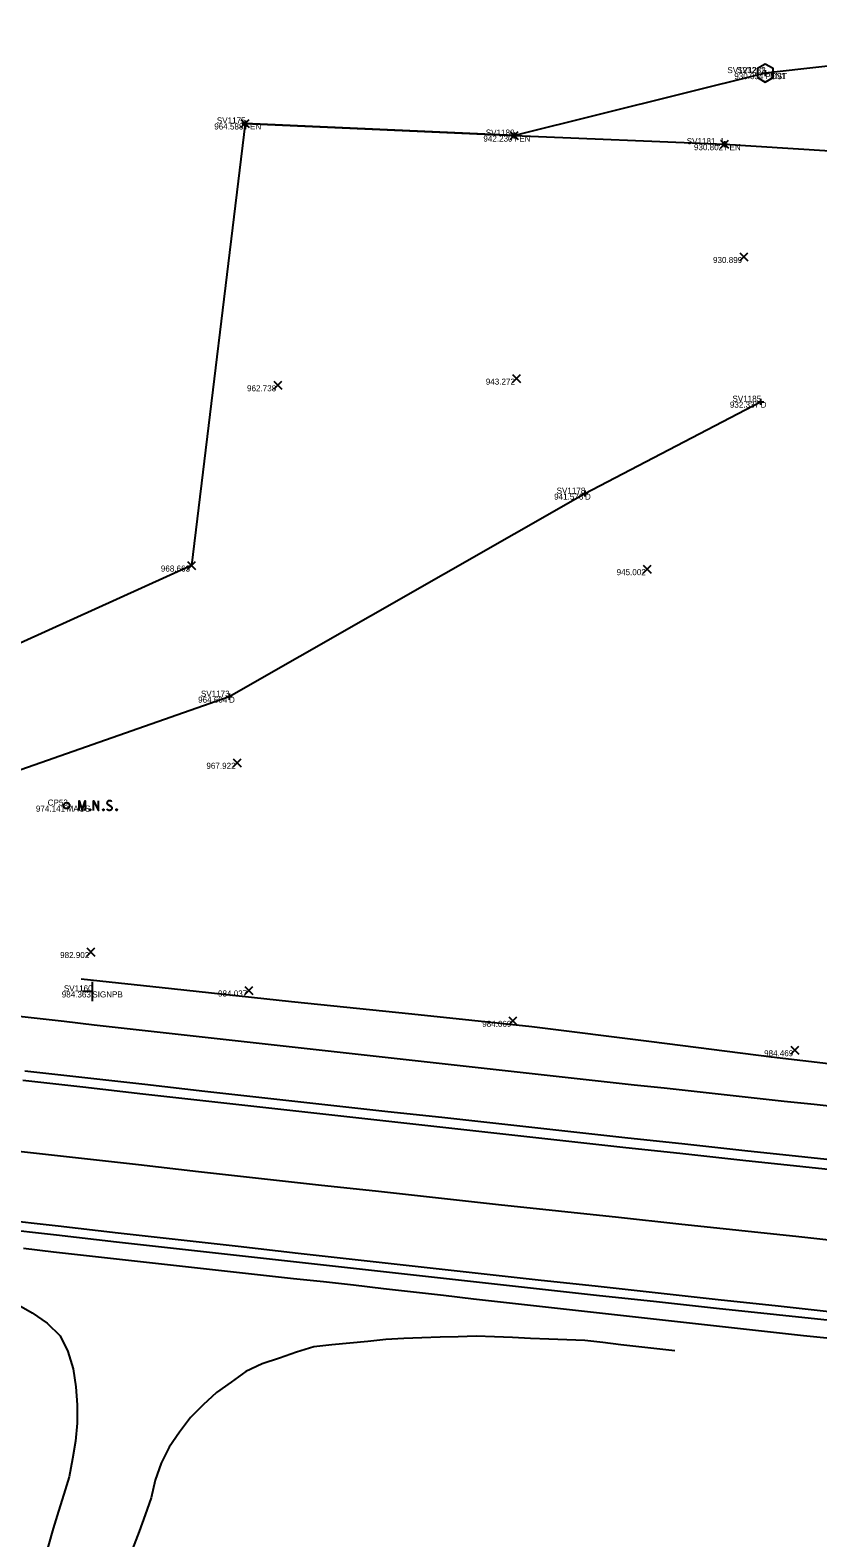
# Model space of a CAD drawing. Extents: x 2065431 to 2068157, y 709104 to 709719.
# Drawn here: x 2067117.5 to 2067248, y 709378.9 to 709628.4 of the extents above; entities that cross this region are included whole.
import ezdxf

# ---------------------------------------------------------------- set-up
doc = ezdxf.new("R2010")
doc.units = 0
for name, color, linetype in [('DT_X_Break_Line', 7, 'Continuous'), ('DT_X_Terrain_Boundary', 7, 'Continuous'), ('PM_X_Edge_Line', 7, 'Continuous'), ('PM_X_Lane_Line', 7, 'Continuous'), ('PV_X_EOP', 7, 'Continuous'), ('PV_X_Shoulder_Rumble_Strip', 7, 'Continuous'), ('RD_X_Fence', 7, 'Continuous'), ('RS_Raster1', 7, 'Continuous'), ('RW_X_CL_100_Bearings', 7, 'Continuous'), ('RW_X_CL_100_Cardinal_Points', 7, 'Continuous'), ('RW_X_CL_100_Curve_Data', 7, 'Continuous'), ('RW_X_CL_100_Distances', 7, 'Continuous'), ('RW_X_Fee_WL', 7, 'Continuous'), ('SV_X_Mon_Cells_Found', 7, 'Continuous'), ('SV_X_Text_Elevation', 7, 'Continuous'), ('SV_X_Text_Name', 7, 'Continuous')]:
    doc.layers.add(name, color=color, linetype=linetype)

msp = doc.modelspace()

# ---------------------------------------------------------------- linework, layer by layer
at = {"layer": 'DT_X_Break_Line'}
msp.add_lwpolyline([(2067498.75, 709430.51), (2067478.87, 709432.67), (2067458.99, 709434.82), (2067439.1, 709436.98), (2067419.22, 709439.13), (2067399.35, 709441.43), (2067379.49, 709443.77), (2067359.59, 709445.77), (2067339.67, 709447.56), (2067319.78, 709449.65), (2067299.9, 709451.81), (2067280.01, 709453.96), (2067260.13, 709456.11), (2067240.26, 709458.41), (2067220.42, 709460.94), (2067200.58, 709463.45), (2067180.69, 709465.52), (2067160.8, 709467.59), (2067140.91, 709469.71), (2067125.91, 709471.33)], dxfattribs=at)
at = {"layer": 'DT_X_Terrain_Boundary'}
msp.add_lwpolyline([(2067560.73, 709418.79), (2067495.34, 709436.29), (2067456.65, 709439.38), (2067410.67, 709443.42), (2067361.02, 709524.1), (2067366.41, 709549.95), (2067373.99, 709596.43), (2067354.6, 709616.29), (2067311.55, 709621.56), (2067309.4, 709622.8), (2067308.24, 709625.52), (2067305.17, 709625.78), (2067302.95, 709628.43), (2067239.24, 709621.32), (2067197.78, 709611.01), (2067153.08, 709612.99), (2067144.2, 709539.81), (2067080.32, 709510.92)], dxfattribs=at)
at = {"layer": 'PM_X_Edge_Line'}
for points in [[(2067116.29, 709454.61), (2067126.22, 709453.49), (2067136.16, 709452.37), (2067146.1, 709451.25), (2067156.04, 709450.14), (2067165.98, 709449.03), (2067175.91, 709447.93), (2067185.85, 709446.83), (2067195.79, 709445.73), (2067205.73, 709444.64), (2067215.67, 709443.55), (2067225.62, 709442.47), (2067235.56, 709441.4), (2067245.5, 709440.32), (2067255.44, 709439.26)], [(2067112.19, 709431.63), (2067122.13, 709430.5), (2067132.07, 709429.37), (2067142, 709428.24), (2067151.94, 709427.12), (2067161.88, 709426), (2067171.81, 709424.89), (2067181.75, 709423.78), (2067191.69, 709422.68), (2067201.63, 709421.58), (2067211.57, 709420.49), (2067221.51, 709419.41), (2067231.45, 709418.33), (2067241.4, 709417.25), (2067251.34, 709416.18)]]:
    msp.add_lwpolyline(points, dxfattribs=at)
at = {"layer": 'PM_X_Lane_Line'}
msp.add_lwpolyline([(2067115.57, 709442.89), (2067125.5, 709441.77), (2067135.44, 709440.64), (2067145.38, 709439.52), (2067155.32, 709438.4), (2067165.25, 709437.3), (2067175.2, 709436.22), (2067185.14, 709435.14), (2067195.08, 709434.06), (2067205.02, 709432.99), (2067214.96, 709431.92), (2067224.91, 709430.85), (2067234.85, 709429.78), (2067244.79, 709428.71), (2067254.74, 709427.65)], dxfattribs=at)
at = {"layer": 'PV_X_EOP'}
for points in [[(2067113.17, 709465.49), (2067118.13, 709464.92), (2067123.1, 709464.36), (2067128.07, 709463.8), (2067133.04, 709463.24), (2067138.01, 709462.69), (2067142.98, 709462.13), (2067147.95, 709461.57), (2067152.92, 709461.02), (2067157.88, 709460.47), (2067162.85, 709459.91), (2067167.82, 709459.36), (2067172.79, 709458.81), (2067177.76, 709458.26), (2067182.73, 709457.71), (2067187.7, 709457.15), (2067192.67, 709456.6), (2067197.64, 709456.05), (2067202.61, 709455.51), (2067207.58, 709454.96), (2067212.55, 709454.41), (2067217.52, 709453.87), (2067222.49, 709453.32), (2067227.46, 709452.78), (2067232.43, 709452.24), (2067237.4, 709451.7), (2067242.37, 709451.16), (2067247.34, 709450.62), (2067252.32, 709450.08)], [(2067116.39, 709426.78), (2067121.36, 709426.22), (2067126.33, 709425.67), (2067131.3, 709425.11), (2067136.27, 709424.56), (2067141.24, 709424.01), (2067146.21, 709423.46), (2067151.18, 709422.91), (2067156.15, 709422.36), (2067161.12, 709421.81), (2067166.09, 709421.27), (2067171.06, 709420.71), (2067176.03, 709420.14), (2067180.99, 709419.57), (2067185.96, 709419.01), (2067190.93, 709418.44), (2067195.9, 709417.88), (2067200.87, 709417.32), (2067205.83, 709416.77), (2067210.8, 709416.21), (2067215.77, 709415.66), (2067220.74, 709415.1), (2067225.71, 709414.55), (2067230.68, 709414), (2067235.65, 709413.46), (2067240.62, 709412.91), (2067245.59, 709412.37), (2067250.56, 709411.83)], [(2067115.24, 709417.59), (2067117.83, 709416.08), (2067120.3, 709414.41), (2067122.45, 709412.31), (2067123.73, 709409.68), (2067124.59, 709406.81), (2067125.06, 709403.85), (2067125.25, 709400.86), (2067125.25, 709397.86), (2067124.99, 709394.88), (2067124.49, 709391.92), (2067123.95, 709388.98), (2067123.07, 709386.11), (2067122.18, 709383.25), (2067121.29, 709380.38), (2067120.45, 709377.5), (2067119.6, 709374.62), (2067118.87, 709371.71), (2067118.45, 709368.75), (2067117.47, 709366.07)], [(2067224.28, 709409.82), (2067221.3, 709410.16), (2067218.32, 709410.49), (2067215.33, 709410.83), (2067212.35, 709411.17), (2067209.37, 709411.5), (2067206.37, 709411.62), (2067203.38, 709411.75), (2067200.38, 709411.87), (2067197.38, 709412), (2067194.38, 709412.12), (2067191.39, 709412.25), (2067188.39, 709412.15), (2067185.39, 709412.05), (2067182.39, 709411.94), (2067179.39, 709411.84), (2067176.4, 709411.68), (2067173.41, 709411.38), (2067170.43, 709411.08), (2067167.45, 709410.78), (2067164.46, 709410.48), (2067161.61, 709409.58), (2067158.77, 709408.61), (2067155.93, 709407.64), (2067153.24, 709406.37), (2067150.8, 709404.63), (2067148.35, 709402.9), (2067146.13, 709400.89), (2067144.04, 709398.75), (2067142.23, 709396.35), (2067140.54, 709393.89), (2067139.21, 709391.2), (2067138.17, 709388.41), (2067137.51, 709385.48), (2067136.52, 709382.66), (2067135.52, 709379.9), (2067134.43, 709377.04)]]:
    msp.add_lwpolyline(points, dxfattribs=at)
at = {"layer": 'PV_X_Shoulder_Rumble_Strip'}
for points in [[(2067116.61, 709456.16), (2067126.55, 709455.04), (2067136.48, 709453.93), (2067146.42, 709452.82), (2067156.36, 709451.71), (2067166.3, 709450.61), (2067176.24, 709449.51), (2067186.18, 709448.42), (2067196.12, 709447.32), (2067206.06, 709446.24), (2067216, 709445.15), (2067225.94, 709444.08), (2067235.88, 709443), (2067245.83, 709441.93), (2067255.77, 709440.87)], [(2067111.93, 709430.13), (2067121.87, 709429.01), (2067131.8, 709427.88), (2067141.74, 709426.76), (2067151.68, 709425.65), (2067161.62, 709424.54), (2067171.55, 709423.43), (2067181.49, 709422.33), (2067191.43, 709421.23), (2067201.37, 709420.14), (2067211.31, 709419.05), (2067221.26, 709417.97), (2067231.2, 709416.89), (2067241.14, 709415.82), (2067251.08, 709414.76)]]:
    msp.add_lwpolyline(points, dxfattribs=at)
at = {"layer": 'RD_X_Fence'}
msp.add_lwpolyline([(2067153.08, 709612.99), (2067197.68, 709610.98), (2067232.51, 709609.56), (2067278.02, 709606.69), (2067296.45, 709582.36), (2067311.18, 709565.23)], dxfattribs=at)
at = {"layer": 'RS_Raster1'}
for p, q in [((2067238.74, 709621.32), (2067239.74, 709621.32)), ((2067239.24, 709621.82), (2067239.24, 709620.82)), ((2067239.24, 709621.32), (2067239.24, 709621.32)), ((2067152.58, 709612.99), (2067153.58, 709612.99)), ((2067153.08, 709613.49), (2067153.08, 709612.49)), ((2067153.08, 709612.99), (2067153.08, 709612.99)), ((2067197.68, 709611.48), (2067197.68, 709610.48)), ((2067197.18, 709610.98), (2067198.18, 709610.98)), ((2067197.68, 709610.98), (2067197.68, 709610.98)), ((2067232.01, 709609.56), (2067233.01, 709609.56)), ((2067232.51, 709610.06), (2067232.51, 709609.06)), ((2067232.51, 709609.56), (2067232.51, 709609.56)), ((2067237.99, 709566.93), (2067238.99, 709566.93)), ((2067238.49, 709567.43), (2067238.49, 709566.43)), ((2067238.49, 709566.93), (2067238.49, 709566.93)), ((2067208.89, 709551.71), (2067209.89, 709551.71)), ((2067209.39, 709552.21), (2067209.39, 709551.21)), ((2067209.39, 709551.71), (2067209.39, 709551.71)), ((2067149.93, 709518.1), (2067150.93, 709518.1)), ((2067150.43, 709518.6), (2067150.43, 709517.6)), ((2067150.43, 709518.1), (2067150.43, 709518.1))]:
    msp.add_line(p, q, dxfattribs=at)
at = {"layer": 'RW_X_CL_100_Bearings'}
for p, q in [((2067152.41, 709612.33), (2067153.74, 709613.66)), ((2067152.41, 709613.66), (2067153.74, 709612.33)), ((2067197.01, 709610.32), (2067198.34, 709611.65)), ((2067197.01, 709611.65), (2067198.34, 709610.32)), ((2067231.84, 709608.89), (2067233.18, 709610.23)), ((2067231.84, 709610.23), (2067233.18, 709608.89)), ((2067235.02, 709590.22), (2067236.35, 709591.56)), ((2067235.02, 709591.56), (2067236.35, 709590.22)), ((2067197.37, 709570.08), (2067198.7, 709571.42)), ((2067197.37, 709571.42), (2067198.7, 709570.08)), ((2067157.84, 709568.98), (2067159.17, 709570.32)), ((2067157.84, 709570.32), (2067159.17, 709568.98)), ((2067143.54, 709539.14), (2067144.87, 709540.48)), ((2067143.54, 709540.48), (2067144.87, 709539.14)), ((2067219.04, 709538.55), (2067220.37, 709539.88)), ((2067219.04, 709539.88), (2067220.37, 709538.55)), ((2067151.09, 709506.49), (2067152.42, 709507.83)), ((2067151.09, 709507.83), (2067152.42, 709506.49)), ((2067126.86, 709475.17), (2067128.19, 709476.5)), ((2067126.86, 709476.5), (2067128.19, 709475.17)), ((2067153.04, 709468.8), (2067154.37, 709470.13)), ((2067153.04, 709470.13), (2067154.37, 709468.8)), ((2067196.79, 709463.77), (2067198.12, 709465.11)), ((2067196.79, 709465.11), (2067198.12, 709463.77)), ((2067243.48, 709458.91), (2067244.81, 709460.24)), ((2067243.48, 709460.24), (2067244.81, 709458.91))]:
    msp.add_line(p, q, dxfattribs=at)
at = {"layer": 'RW_X_CL_100_Cardinal_Points'}
for p, q in [((2067127.78, 709469.31), (2067126.18, 709469.31)), ((2067127.78, 709470.91), (2067127.78, 709467.71))]:
    msp.add_line(p, q, dxfattribs=at)
at = {"layer": 'RW_X_CL_100_Curve_Data'}
for points in [[(2067125.61, 709499.27), (2067125.61, 709500.87), (2067126.12, 709499.27), (2067126.6, 709500.87), (2067126.6, 709499.27)], [(2067127.38, 709499.49), (2067127.43, 709499.49), (2067127.46, 709499.46), (2067127.5, 709499.41), (2067127.5, 709499.35), (2067127.46, 709499.3), (2067127.43, 709499.27), (2067127.38, 709499.27), (2067127.34, 709499.3), (2067127.31, 709499.35), (2067127.31, 709499.41), (2067127.34, 709499.46), (2067127.38, 709499.49)], [(2067127.98, 709499.27), (2067127.98, 709500.87), (2067128.81, 709499.27), (2067128.81, 709500.87)], [(2067129.59, 709499.49), (2067129.65, 709499.49), (2067129.68, 709499.46), (2067129.71, 709499.41), (2067129.71, 709499.35), (2067129.68, 709499.3), (2067129.65, 709499.27), (2067129.59, 709499.27), (2067129.56, 709499.3), (2067129.52, 709499.35), (2067129.52, 709499.41), (2067129.56, 709499.46), (2067129.59, 709499.49)], [(2067130.96, 709500.76), (2067130.94, 709500.79), (2067130.9, 709500.81), (2067130.8, 709500.85), (2067130.68, 709500.87), (2067130.59, 709500.87), (2067130.56, 709500.87), (2067130.42, 709500.84), (2067130.3, 709500.76), (2067130.22, 709500.66), (2067130.2, 709500.56), (2067130.2, 709500.48), (2067130.22, 709500.38), (2067130.31, 709500.29), (2067130.91, 709499.92), (2067130.97, 709499.87), (2067130.99, 709499.82), (2067131.01, 709499.74), (2067131.01, 709499.67), (2067131, 709499.59), (2067130.99, 709499.54), (2067130.97, 709499.48), (2067130.95, 709499.43), (2067130.92, 709499.39), (2067130.89, 709499.35), (2067130.86, 709499.32), (2067130.81, 709499.3), (2067130.78, 709499.29), (2067130.68, 709499.27), (2067130.53, 709499.27), (2067130.43, 709499.3), (2067130.29, 709499.39), (2067130.2, 709499.46)], [(2067131.77, 709499.49), (2067131.83, 709499.49), (2067131.86, 709499.46), (2067131.89, 709499.41), (2067131.89, 709499.35), (2067131.86, 709499.3), (2067131.83, 709499.27), (2067131.77, 709499.27), (2067131.74, 709499.3), (2067131.71, 709499.35), (2067131.71, 709499.41), (2067131.74, 709499.46), (2067131.77, 709499.49)]]:
    msp.add_lwpolyline(points, dxfattribs=at)
msp.add_circle((2067123.52, 709500.07), 0.497, dxfattribs=at)
at = {"layer": 'RW_X_CL_100_Distances'}
msp.add_lwpolyline([(2067237.94, 709620.57), (2067239.24, 709619.82), (2067240.54, 709620.57), (2067240.54, 709622.07), (2067239.24, 709622.82), (2067237.94, 709622.07), (2067237.94, 709620.57)], dxfattribs=at)
at = {"layer": 'RW_X_Fee_WL'}
msp.add_lwpolyline([(2066980.58, 709498.86), (2067014.05, 709495.27), (2067044.47, 709492.22), (2067084.68, 709495.12), (2067150.43, 709518.1), (2067209.39, 709551.71), (2067238.49, 709566.93)], dxfattribs=at)

# ---------------------------------------------------------------- texts
at = {"layer": 'SV_X_Mon_Cells_Found'}
for s, p in [('SV1232_1', (2067232.98, 709621.32)), ('SV1232', (2067234.57, 709621.32)), ('SV1175', (2067148.41, 709612.99)), ('SV1180', (2067192.96, 709610.98)), ('SV1181_1', (2067226.25, 709609.56)), ('SV1185', (2067233.82, 709566.93)), ('SV1178', (2067204.69, 709551.71)), ('SV1173', (2067145.77, 709518.1)), ('CP53', (2067120.39, 709500.07)), ('SV1160', (2067123.07, 709469.31))]:
    msp.add_text(s, height=1, dxfattribs=at).set_placement(p)
at = {"layer": 'SV_X_Text_Elevation'}
for s, p in [('POST', (2067239.24, 709620.32)), ('FEN1', (2067239.24, 709620.32)), ('FEN', (2067153.08, 709611.99)), ('FEN', (2067197.68, 709609.98)), ('FEN', (2067232.51, 709608.56)), ('D', (2067238.49, 709565.93)), ('D', (2067209.39, 709550.71)), ('D', (2067150.43, 709517.1)), ('MAGS', (2067123.52, 709499.07)), ('SIGNPB', (2067127.78, 709468.31))]:
    msp.add_text(s, height=1, dxfattribs=at).set_placement(p)
at = {"layer": 'SV_X_Text_Name'}
for s, p in [('930.054', (2067234.12, 709620.32)), ('930.054', (2067234.12, 709620.32)), ('964.588', (2067147.98, 709611.99)), ('964.588', (2067147.98, 709611.99)), ('942.230', (2067192.56, 709609.98)), ('942.230', (2067192.56, 709609.98)), ('930.802', (2067227.44, 709608.56)), ('930.802', (2067227.44, 709608.56)), ('930.899', (2067230.6, 709589.89)), ('962.738', (2067153.41, 709568.65)), ('943.272', (2067192.96, 709569.75)), ('932.337', (2067233.39, 709565.93)), ('941.576', (2067204.28, 709550.71)), ('968.663', (2067139.14, 709538.81)), ('945.002', (2067214.63, 709538.21)), ('964.604', (2067145.31, 709517.1)), ('967.922', (2067146.68, 709506.16)), ('974.141', (2067118.44, 709499.07)), ('982.902', (2067122.45, 709474.83)), ('984.363', (2067122.72, 709468.31)), ('984.037', (2067148.61, 709468.47)), ('984.069', (2067192.37, 709463.44)), ('984.469', (2067239.06, 709458.58))]:
    msp.add_text(s, height=1, dxfattribs=at).set_placement(p)

doc.saveas('drawing.dxf')
